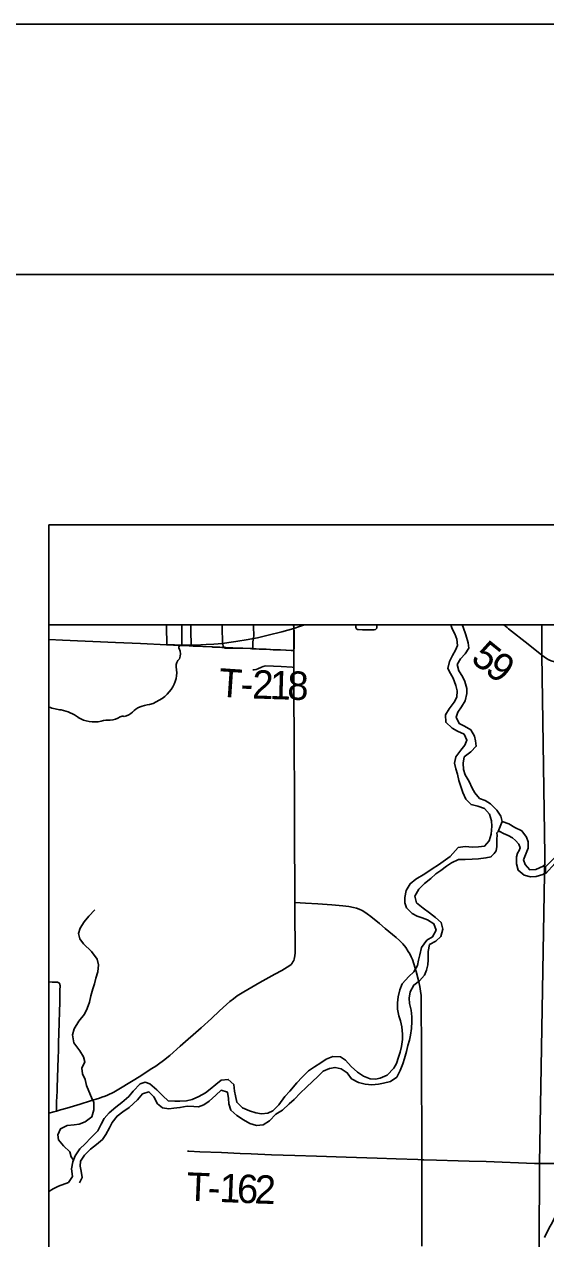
# Model space of a CAD drawing. Extents: x 0 to 34, y 0 to 22.
# Drawn here: x 1.951 to 2.992, y 19.573 to 22 of the extents above; entities that cross this region are included whole.
import ezdxf

# ---------------------------------------------------------------- set-up
doc = ezdxf.new("R2010")
doc.units = 0
for name, color, linetype in [('Default', 7, 'Continuous'), ('GM_X_City_Street', 7, 'Continuous'), ('GM_X_County_Road', 7, 'Continuous'), ('GM_X_County_Road_Text', 7, 'Continuous'), ('GM_X_Interchange_Ramps', 7, 'Continuous'), ('GM_X_Section', 7, 'Continuous'), ('GM_X_Section_Text', 7, 'Continuous'), ('GM_X_Township_Road_Text', 7, 'Continuous'), ('GM_X_US_Location', 7, 'Continuous'), ('SH_Cut_Line', 7, 'Continuous'), ('SH_Data', 7, 'Continuous'), ('SH_Text', 7, 'Continuous')]:
    doc.layers.add(name, color=color, linetype=linetype)

msp = doc.modelspace()

# ---------------------------------------------------------------- linework, layer by layer
at = {"layer": 'Default'}
for points in [[(2.2656, 20.7623), (2.2656, 20.7623), (2.2656, 20.7623), (2.2656, 20.8), (2, 20.8), (2, 20.6353)], [(2.9623, 15.7101), (2.9708, 17.6769), (2.9753, 18.7199), (2.9796, 19.7242), (2.9904, 20.3395), (2.984, 20.7397), (2.9842, 20.8), (2, 20.8), (2, 15.7064)], [(8.1282, 20.8), (2.9842, 20.8), (2.984, 20.7397), (2.9904, 20.3395), (2.9796, 19.7242), (2.9753, 18.7199), (2.9708, 17.6769), (2.9623, 15.7101)]]:
    msp.add_lwpolyline(points, dxfattribs=at)
msp.add_lwpolyline([(2.4885, 20.8), (2.2349, 20.8), (2.2349, 20.7991), (2.2349, 20.7968), (2.2349, 20.791), (2.235, 20.7884), (2.2351, 20.7677), (2.2351, 20.7657), (2.2352, 20.76), (2.2352, 20.7599), (2.2383, 20.7598), (2.2593, 20.7588), (2.2801, 20.7578), (2.2877, 20.7575), (2.3259, 20.7557), (2.3275, 20.7556), (2.3276, 20.7556), (2.3409, 20.755), (2.3451, 20.7548), (2.3451, 20.7548), (2.3497, 20.7546), (2.3532, 20.7544), (2.3648, 20.7539), (2.367, 20.7538), (2.3821, 20.7532), (2.4016, 20.7524), (2.4053, 20.7522), (2.4078, 20.7521), (2.4105, 20.752), (2.414, 20.7518), (2.4195, 20.7516), (2.4337, 20.751), (2.448, 20.7503), (2.4622, 20.7497), (2.4837, 20.7488), (2.4846, 20.7488), (2.4893, 20.7486), (2.4894, 20.7543), (2.4895, 20.7707), (2.4896, 20.7836), (2.4896, 20.7867), (2.4888, 20.7931)], close=True, dxfattribs=at)
for centre, major_axis, start_param, end_param in [((2.2648, 20.7546), (0.00568, 0), 1.883978, 3.671073), ((2.2286, 20.7414), (0.0341, 0), 5.934695, 6.695948), ((2.2617, 20.7619), (0.00393, 0), 5.05454, 6.418171), ((2.2788, 20.7185), (0.0248, 0), 2.387724, 3.262537), ((2.1678, 20.7052), (0.0874, 0), 5.101753, 6.440018), ((2.0803, 20.8267), (0.2524, 0), 4.388741, 4.488961), ((2.005, 20.5686), (0.079, 0), 0.823519, 1.323587), ((2.2047, 20.6023), (0.0479, 0), 1.647645, 2.488434), ((2.0904, 20.6459), (0.0501, 0), 4.026481, 4.996735), ((2.1194, 20.5767), (0.0412, 0), 1.495662, 1.94098), ((2.123, 20.6309), (0.0267, 0), 4.691044, 5.507374), ((2.1472, 20.6116), (0.00752, 0), 1.147584, 2.315152), ((2.144, 20.6391), (0.0282, 0), 4.937069, 5.64225)]:
    msp.add_ellipse(centre, major_axis=major_axis, ratio=0.8, start_param=start_param, end_param=end_param, dxfattribs=at)
at = {"layer": 'GM_X_City_Street'}
for points in [[(2.9842, 20.7391), (2.9933, 20.7327), (2.998, 20.7298), (3.0028, 20.7277), (3.0094, 20.7263), (3.0216, 20.7257), (3.0993, 20.7282), (3.1707, 20.7304), (3.2689, 20.7337)], [(2.0148, 19.8284), (2.0234, 19.8309), (2.0354, 19.8341), (2.0622, 19.8421), (2.0829, 19.8485), (2.1007, 19.8541), (2.1054, 19.8558), (2.1125, 19.8584), (2.1168, 19.8602), (2.1212, 19.8621), (2.1254, 19.8643), (2.1294, 19.8663), (2.1428, 19.8742), (2.1832, 19.899), (2.1939, 19.906), (2.2056, 19.9134), (2.2131, 19.9182), (2.2189, 19.9222), (2.229, 19.9296), (2.2411, 19.9394), (2.2622, 19.9578), (2.3041, 19.9947), (2.3248, 20.0136), (2.3406, 20.0285), (2.3542, 20.0412), (2.3612, 20.0472), (2.3685, 20.0529), (2.3761, 20.0583), (2.3892, 20.0665), (2.4214, 20.0853), (2.4511, 20.102), (2.4647, 20.1095), (2.4756, 20.1157), (2.4809, 20.1191), (2.4834, 20.1212), (2.4855, 20.1236), (2.4873, 20.1262), (2.4887, 20.1291), (2.4898, 20.1321), (2.4906, 20.1352), (2.491, 20.1383), (2.4915, 20.1446), (2.4916, 20.154), (2.491, 20.2223), (2.4911, 20.2448)], [(2, 19.8242), (2.0095, 19.8268), (2.0148, 19.8284)]]:
    msp.add_lwpolyline(points, dxfattribs=at)
at = {"layer": 'GM_X_County_Road'}
for points in [[(2.489, 20.7925), (2.5001, 20.7964), (2.5101, 20.8)], [(2.3467, 20.7628), (2.3595, 20.7645), (2.3731, 20.7666), (2.3977, 20.7708), (2.4084, 20.7728), (2.4162, 20.7743), (2.4377, 20.779), (2.4651, 20.7859), (2.489, 20.7925)], [(2.489, 20.7488), (2.489, 20.7813), (2.489, 20.7925)], [(2, 20.7704), (2.0273, 20.7694), (2.1329, 20.7647), (2.1825, 20.7625), (2.2355, 20.7602)], [(2.2355, 20.7602), (2.2509, 20.7597), (2.2729, 20.7594), (2.2838, 20.7595), (2.2918, 20.7596), (2.3138, 20.7607), (2.3295, 20.7615), (2.3467, 20.7628)], [(2.6715, 20.1934), (2.6599, 20.2032), (2.643, 20.2169), (2.6356, 20.2225), (2.6305, 20.2258), (2.6251, 20.2289), (2.6196, 20.2315), (2.6138, 20.2336), (2.6079, 20.2352), (2.5988, 20.237), (2.5865, 20.2386), (2.5649, 20.2406), (2.537, 20.2423), (2.5121, 20.2437), (2.4911, 20.2448), (2.491, 20.3018), (2.4906, 20.3422), (2.4903, 20.4511), (2.4902, 20.4947), (2.4898, 20.5227), (2.4895, 20.5818), (2.4893, 20.6503), (2.489, 20.715), (2.4889, 20.7281), (2.489, 20.7488)], [(2.7434, 20.0136), (2.7433, 20.0186), (2.7434, 20.0466), (2.743, 20.059), (2.7422, 20.0682), (2.7408, 20.0773), (2.7381, 20.0894), (2.7333, 20.1074), (2.7289, 20.1223), (2.7258, 20.131), (2.7234, 20.1367), (2.7207, 20.1422), (2.7176, 20.1475), (2.7124, 20.1552), (2.7065, 20.1623), (2.7001, 20.1689), (2.6932, 20.1752), (2.6715, 20.1934)], [(2.7443, 19.5586), (2.7443, 19.5773), (2.7443, 19.6239), (2.7444, 19.655), (2.7447, 19.7078), (2.7447, 19.7311), (2.7446, 19.7576), (2.7444, 19.8198), (2.7441, 19.8602), (2.7441, 19.8757), (2.7442, 19.8974), (2.7441, 19.9285), (2.7439, 19.9533), (2.7437, 19.9813), (2.7434, 20.0136)]]:
    msp.add_lwpolyline(points, dxfattribs=at)
at = {"layer": 'GM_X_Interchange_Ramps'}
for p, q in [((2.489, 20.7925), (2.4887, 20.8)), ((2.9147, 20.7948), (2.9085, 20.8))]:
    msp.add_line(p, q, dxfattribs=at)
for points in [[(2.6129, 20.8), (2.6129, 20.7959), (2.6131, 20.7944), (2.6135, 20.7932), (2.6141, 20.7922), (2.6148, 20.7915), (2.6158, 20.7908), (2.6174, 20.7903), (2.6263, 20.7899), (2.643, 20.7898), (2.6495, 20.7901), (2.6519, 20.7908), (2.6534, 20.7918), (2.654, 20.7926), (2.6544, 20.7936), (2.6544, 20.7952), (2.6544, 20.7985), (2.6544, 20.8)], [(2.9842, 20.7391), (2.9568, 20.7611), (2.9178, 20.7921), (2.9147, 20.7948)], [(2.3495, 20.7544), (2.3504, 20.7539), (2.3515, 20.7535), (2.3532, 20.7534), (2.3573, 20.7533), (2.362, 20.7532), (2.3714, 20.7533), (2.387, 20.7532), (2.4072, 20.7525)], [(2.4072, 20.7525), (2.412, 20.7523), (2.489, 20.7488)], [(2.4073, 20.7103), (2.4101, 20.7103), (2.4138, 20.7107), (2.4174, 20.7117), (2.4245, 20.7155), (2.4275, 20.7167), (2.4302, 20.7176), (2.4333, 20.718), (2.4639, 20.7165), (2.4857, 20.7152), (2.489, 20.715)], [(2.0148, 19.8284), (2.0151, 19.8346), (2.0154, 19.8469), (2.0163, 19.8684), (2.0167, 19.8776), (2.0171, 19.8929), (2.0177, 19.9175), (2.0182, 19.9329), (2.0189, 19.9514), (2.0193, 19.9668), (2.0197, 19.9822), (2.0203, 20.0067), (2.0208, 20.0254), (2.0215, 20.047), (2.0215, 20.0531), (2.0215, 20.059), (2.0217, 20.0652), (2.0219, 20.0713), (2.0221, 20.0775), (2.0221, 20.0785), (2.0221, 20.0794), (2.0219, 20.0809), (2.0216, 20.082), (2.021, 20.0833), (2.0202, 20.0844), (2.0196, 20.0849), (2.0187, 20.0854), (2.0175, 20.0858), (2.0157, 20.0859), (2.0125, 20.0859), (2.0094, 20.086), (2.0066, 20.0861), (2, 20.0864)], [(2.2767, 19.748), (2.2795, 19.748), (2.3012, 19.747), (2.3447, 19.7454), (2.382, 19.7438), (2.4038, 19.7428), (2.4442, 19.7412), (2.4908, 19.7396), (2.5344, 19.7383), (2.5935, 19.7362), (2.6556, 19.7339), (2.693, 19.7327), (2.7365, 19.7316), (2.7447, 19.7311)], [(2.7447, 19.7311), (2.7488, 19.7309), (2.7738, 19.7302), (2.8173, 19.7288), (2.8391, 19.7283), (2.8733, 19.7273), (2.9696, 19.7238), (2.9798, 19.7237)], [(2.9798, 19.7237), (3.0111, 19.7234), (3.0768, 19.7245), (3.1986, 19.7278), (3.2517, 19.7291), (3.2599, 19.7293)]]:
    msp.add_lwpolyline(points, dxfattribs=at)
at = {"layer": 'GM_X_Section'}
msp.add_line((2.9913, 20.3162), (2.9912, 20.3023), dxfattribs=at)
for points in [[(2.905, 20.407), (2.8971, 20.3869)], [(2.8971, 20.3869), (2.9003, 20.3867), (2.9078, 20.3828), (2.9172, 20.3792), (2.9259, 20.3746), (2.9319, 20.3692), (2.9382, 20.3619), (2.9412, 20.3542), (2.9388, 20.3493), (2.9357, 20.3437), (2.9337, 20.3361)], [(2.905, 20.407), (2.9182, 20.4024), (2.9301, 20.3949), (2.944, 20.3886), (2.9536, 20.3758), (2.9571, 20.3663), (2.9569, 20.3534), (2.9473, 20.3306)], [(2.9337, 20.3361), (2.9339, 20.3221), (2.9368, 20.3095), (2.9488, 20.2999), (2.9613, 20.2967), (2.9727, 20.2969), (2.986, 20.3009), (2.9913, 20.3044)], [(2.9912, 20.3023), (3.0108, 20.324), (3.021, 20.3271), (3.0324, 20.3275), (3.0419, 20.3276), (3.054, 20.3253), (3.0677, 20.322), (3.0806, 20.3205), (3.0904, 20.3228), (3.1024, 20.3388)], [(3.0139, 20.3392), (2.9913, 20.3162)], [(2.9473, 20.3306), (2.9506, 20.3211), (2.9599, 20.3107), (2.9725, 20.3113), (2.9866, 20.3176), (2.9913, 20.322)], [(2.0488, 19.7303), (2.0445, 19.7366), (2.0416, 19.7468), (2.0293, 19.7591), (2.0192, 19.771), (2.0178, 19.7809), (2.0233, 19.793), (2.0366, 19.7996), (2.0503, 19.8006), (2.0606, 19.8024), (2.0724, 19.8067), (2.0855, 19.8168), (2.0898, 19.8308), (2.0893, 19.8452), (2.0852, 19.8555), (2.0797, 19.8681), (2.0749, 19.8795), (2.072, 19.8917), (2.0673, 19.9028), (2.0659, 19.9138), (2.0714, 19.927), (2.0689, 19.9365), (2.0614, 19.9484), (2.0499, 19.9649), (2.0467, 19.9805), (2.0503, 19.9926), (2.06, 20.008), (2.0708, 20.0219), (2.0766, 20.0336), (2.081, 20.046), (2.0838, 20.0585), (2.0878, 20.0725), (2.091, 20.0823), (2.0938, 20.094), (2.0974, 20.1065), (2.0987, 20.1205), (2.0962, 20.1319), (2.085, 20.1473), (2.0693, 20.1623), (2.0614, 20.1722), (2.0593, 20.1833), (2.0621, 20.1938), (2.0703, 20.2063), (2.0795, 20.2179), (2.0918, 20.2306)], [(2.9892, 19.5756), (2.9989, 19.5947), (3.0046, 19.6053), (3.0106, 19.6175), (3.0178, 19.627), (3.0291, 19.6395), (3.034, 19.6525), (3.0351, 19.6661), (3.0358, 19.6858), (3.0369, 19.6976), (3.038, 19.7071), (3.0391, 19.7196), (3.0466, 19.731), (3.0603, 19.7379), (3.0724, 19.7436), (3.0769, 19.7561), (3.0731, 19.7686), (3.0677, 19.7808)]]:
    msp.add_lwpolyline(points, dxfattribs=at)
at = {"layer": 'GM_X_Section_Text'}
for points in [[(2.8024, 20.8), (2.8052, 20.7921), (2.8103, 20.7822), (2.8142, 20.7715), (2.8159, 20.7589), (2.8115, 20.7491), (2.806, 20.739), (2.7997, 20.7269), (2.7967, 20.713), (2.8018, 20.703), (2.8069, 20.6934), (2.8127, 20.6784), (2.8151, 20.6681), (2.8144, 20.6552), (2.8093, 20.6455), (2.7992, 20.6324), (2.7921, 20.6204), (2.7922, 20.6052), (2.8052, 20.5935), (2.8157, 20.5876), (2.8288, 20.5816), (2.8346, 20.5694), (2.8306, 20.5596), (2.8224, 20.5495), (2.8123, 20.5364), (2.8101, 20.5235), (2.8126, 20.5125), (2.8157, 20.5018), (2.8185, 20.4892), (2.8221, 20.4792), (2.8267, 20.4647), (2.8321, 20.4513), (2.8429, 20.4408), (2.8564, 20.4379), (2.87, 20.433), (2.8799, 20.4214), (2.8834, 20.4084), (2.8843, 20.3974), (2.8833, 20.3815), (2.8788, 20.3683), (2.8699, 20.3578), (2.8577, 20.3562), (2.846, 20.3557), (2.8309, 20.3568), (2.8168, 20.3548), (2.8009, 20.3372)], [(2.905, 20.407), (2.9022, 20.4179), (2.8941, 20.4299), (2.8819, 20.4423), (2.8707, 20.4486), (2.8598, 20.453), (2.8502, 20.4642), (2.8454, 20.4738), (2.8389, 20.4872), (2.8312, 20.4999), (2.8277, 20.511), (2.8272, 20.5232), (2.8293, 20.536), (2.8424, 20.5464), (2.8533, 20.5572), (2.8516, 20.5679), (2.8495, 20.5778), (2.8422, 20.5901), (2.8299, 20.5976), (2.819, 20.6027), (2.8132, 20.6154), (2.8165, 20.6252), (2.8239, 20.636), (2.831, 20.6484), (2.8343, 20.6628), (2.8341, 20.6727), (2.8303, 20.6868), (2.8255, 20.6964), (2.8186, 20.7083), (2.8151, 20.7209), (2.8221, 20.7322), (2.8314, 20.7422), (2.8385, 20.7535), (2.8368, 20.7638), (2.8322, 20.7802), (2.8272, 20.7951), (2.8254, 20.8)], [(2.8832, 20.3369), (2.889, 20.3432), (2.8929, 20.3484), (2.8945, 20.3568), (2.8946, 20.3644), (2.8944, 20.3723), (2.8948, 20.3788), (2.8945, 20.3845), (2.8971, 20.3869)], [(2.8971, 20.3869), (2.905, 20.407)], [(2.8009, 20.3372), (2.7871, 20.3271), (2.7776, 20.3204), (2.7649, 20.3126), (2.7504, 20.3026), (2.7324, 20.2914), (2.7213, 20.2825), (2.7135, 20.2689), (2.7107, 20.2553), (2.7105, 20.2447), (2.7142, 20.2344), (2.7254, 20.2229), (2.7352, 20.2178), (2.745, 20.2142), (2.7556, 20.2103), (2.7687, 20.2025), (2.7735, 20.1896), (2.7661, 20.1764), (2.7543, 20.1697), (2.7442, 20.1551), (2.7406, 20.1407), (2.7378, 20.1301), (2.7357, 20.1195), (2.7287, 20.1067), (2.7188, 20.0974), (2.7053, 20.0824), (2.7006, 20.0707), (2.6973, 20.0567), (2.6957, 20.0449), (2.6962, 20.032), (2.6987, 20.0187), (2.702, 20.0084), (2.7049, 19.9966), (2.7062, 19.9818), (2.7057, 19.9716), (2.704, 19.9576), (2.7015, 19.9462), (2.6983, 19.936), (2.694, 19.9236), (2.6889, 19.9138), (2.6751, 19.8999), (2.6614, 19.8944), (2.6518, 19.8919), (2.6412, 19.8928), (2.6284, 19.8979), (2.616, 19.906), (2.6032, 19.9176), (2.592, 19.9302), (2.5819, 19.9368), (2.5671, 19.9374), (2.5537, 19.9319), (2.5426, 19.9248), (2.53, 19.917), (2.5185, 19.9085), (2.5054, 19.8961), (2.4947, 19.8849), (2.4811, 19.8684), (2.4711, 19.8571), (2.4588, 19.841), (2.4468, 19.8286), (2.4373, 19.8238), (2.4247, 19.8225), (2.413, 19.8245), (2.4005, 19.8285), (2.3866, 19.8351), (2.375, 19.8459), (2.3725, 19.8588), (2.3707, 19.8684), (2.369, 19.8817), (2.3581, 19.8917), (2.3437, 19.8903), (2.3333, 19.8814), (2.3222, 19.872), (2.3126, 19.865), (2.2996, 19.8576), (2.2859, 19.8513), (2.2745, 19.8488), (2.2616, 19.8478), (2.2513, 19.8483), (2.238, 19.8489), (2.2276, 19.8589), (2.2156, 19.8708), (2.2017, 19.8828), (2.1919, 19.8863), (2.182, 19.8827), (2.1681, 19.8681), (2.1596, 19.8575), (2.1454, 19.8452), (2.1335, 19.8363), (2.1201, 19.8247), (2.1105, 19.8138), (2.1042, 19.8021), (2.0976, 19.789), (2.0837, 19.7747), (2.0722, 19.7631), (2.0618, 19.7526), (2.0525, 19.7391), (2.0474, 19.727), (2.0453, 19.713), (2.047, 19.6974), (2.0389, 19.6854)], [(2.8175, 20.3307), (2.8308, 20.3307), (2.8449, 20.332), (2.8574, 20.3326), (2.8726, 20.3343), (2.8829, 20.3364), (2.8832, 20.3369)], [(2.0609, 19.6851), (2.066, 19.6953), (2.0646, 19.7082), (2.0625, 19.7185), (2.063, 19.7283), (2.0707, 19.74), (2.0831, 19.752), (2.0949, 19.7617), (2.1068, 19.7718), (2.1138, 19.7815), (2.1208, 19.7947), (2.1263, 19.8056), (2.1359, 19.8184), (2.1478, 19.8266), (2.1605, 19.8355), (2.1766, 19.8505), (2.187, 19.8625), (2.1996, 19.8669), (2.2097, 19.8569), (2.2167, 19.8431), (2.2268, 19.8346), (2.2397, 19.8329), (2.2492, 19.834), (2.2614, 19.8353), (2.2762, 19.8378), (2.2891, 19.8372), (2.2986, 19.8367), (2.3093, 19.8407), (2.3196, 19.8482), (2.333, 19.8598), (2.3442, 19.8699), (2.3563, 19.8663), (2.3584, 19.8533), (2.359, 19.8431), (2.3634, 19.8301), (2.3754, 19.8197), (2.3882, 19.8105), (2.4013, 19.8038), (2.4146, 19.7995), (2.4275, 19.8008), (2.4401, 19.809), (2.4528, 19.8221), (2.4666, 19.8303), (2.4797, 19.8426), (2.4896, 19.8512), (2.5023, 19.8647), (2.5139, 19.8755), (2.5266, 19.8879), (2.5362, 19.8969), (2.5477, 19.9081), (2.5603, 19.9132), (2.5713, 19.9157), (2.5838, 19.9129), (2.5955, 19.9048), (2.604, 19.8929), (2.618, 19.8855), (2.6312, 19.8823), (2.6445, 19.881), (2.6578, 19.8823), (2.6677, 19.8841), (2.6817, 19.8873), (2.6944, 19.8959), (2.7014, 19.9094), (2.7065, 19.923), (2.7097, 19.9336), (2.7137, 19.9472), (2.7169, 19.9593), (2.7197, 19.9703), (2.7217, 19.9801), (2.7238, 19.9933), (2.7247, 20.007), (2.7249, 20.0169), (2.7231, 20.0298), (2.7199, 20.0431), (2.7193, 20.0537), (2.7214, 20.0666), (2.7284, 20.0802), (2.7399, 20.0887), (2.7499, 20.1), (2.7542, 20.1102), (2.7566, 20.1204), (2.7571, 20.1302), (2.757, 20.1469), (2.7602, 20.1609), (2.7725, 20.168), (2.7828, 20.1769), (2.7864, 20.1921), (2.7832, 20.205), (2.772, 20.2154), (2.7596, 20.2243), (2.7475, 20.2336), (2.734, 20.2447), (2.7308, 20.2577), (2.7386, 20.2716), (2.7501, 20.2828), (2.7628, 20.2933), (2.7728, 20.3023), (2.7827, 20.309), (2.7938, 20.3175), (2.8038, 20.3242), (2.8175, 20.3307)], [(2.0389, 19.6854), (2.0191, 19.6781), (2.0087, 19.6729), (2, 19.6674)]]:
    msp.add_lwpolyline(points, dxfattribs=at)
at = {"layer": 'GM_X_US_Location'}
for points in [[(2.2838, 20.7595), (2.2838, 20.7616), (2.2835, 20.7858), (2.2833, 20.8)], [(2.3495, 20.7544), (2.3483, 20.7559), (2.3476, 20.7579), (2.347, 20.7604), (2.3467, 20.7628), (2.3459, 20.7961), (2.3459, 20.8)], [(2.4072, 20.7525), (2.4072, 20.7543), (2.4072, 20.7624), (2.4074, 20.7659), (2.4077, 20.7691), (2.4084, 20.7728), (2.4085, 20.7744), (2.4088, 20.7773), (2.4088, 20.78), (2.4088, 20.7834), (2.4085, 20.7916), (2.4083, 20.7988), (2.4083, 20.8)]]:
    msp.add_lwpolyline(points, dxfattribs=at)
at = {"layer": 'SH_Cut_Line'}
for q in [(2, 14), (9, 21)]:
    msp.add_line((2, 21), q, dxfattribs=at)
at = {"layer": 'SH_Data'}
msp.add_lwpolyline([(1.5, 21.5), (33.5, 21.5), (33.5, 0.5), (1.5, 0.5)], close=True, dxfattribs=at)
at = {"layer": 'SH_Text'}
for points in [[(0, 0), (34, 0), (34, 22), (0, 22)], [(2.9842, 20.8), (2, 20.8), (2, 14), (2.9377, 14), (2.9479, 14.7065), (2.9623, 15.7101), (2.9708, 17.6769), (2.9753, 18.7199), (2.9796, 19.7242), (2.9904, 20.3395), (2.984, 20.7397)], [(2.9377, 14), (8.8, 14), (8.8, 20.8), (2.9842, 20.8), (2.984, 20.7397), (2.9904, 20.3395), (2.9796, 19.7242), (2.9753, 18.7199), (2.9708, 17.6769), (2.9623, 15.7101), (2.9479, 14.7065)]]:
    msp.add_lwpolyline(points, close=True, dxfattribs=at)

# ---------------------------------------------------------------- texts
at = {"layer": 'GM_X_County_Road_Text'}
for s, rotation, p in [('5', 321.1588, (2.8399, 20.7286)), ('9', 322.0863, (2.8679, 20.706)), ('T', 356.1101, (2.3374, 20.6568)), ('2', 358.1133, (2.4053, 20.6529)), ('1', 358.2186, (2.4404, 20.6517)), ('8', 358.2566, (2.4754, 20.6506)), ('-', 357.8352, (2.3817, 20.6538)), ('T', 357.7109, (2.2738, 19.6493)), ('1', 357.7155, (2.3396, 19.6467)), ('6', 357.7466, (2.3746, 19.6453)), ('2', 357.9278, (2.4098, 19.6439)), ('-', 357.7092, (2.3163, 19.6476))]:
    msp.add_text(s, height=0.0568, rotation=rotation, dxfattribs=at).set_placement(p)
at = {"layer": 'GM_X_Township_Road_Text'}
msp.add_text('309', height=0.000189, rotation=0, dxfattribs=at).set_placement((2.0303, 20.7314))
for s in ['s', 'r']:
    msp.add_text(s, height=0.000189, dxfattribs=at).set_placement((2.0971, 20.7452))

doc.saveas('drawing.dxf')
